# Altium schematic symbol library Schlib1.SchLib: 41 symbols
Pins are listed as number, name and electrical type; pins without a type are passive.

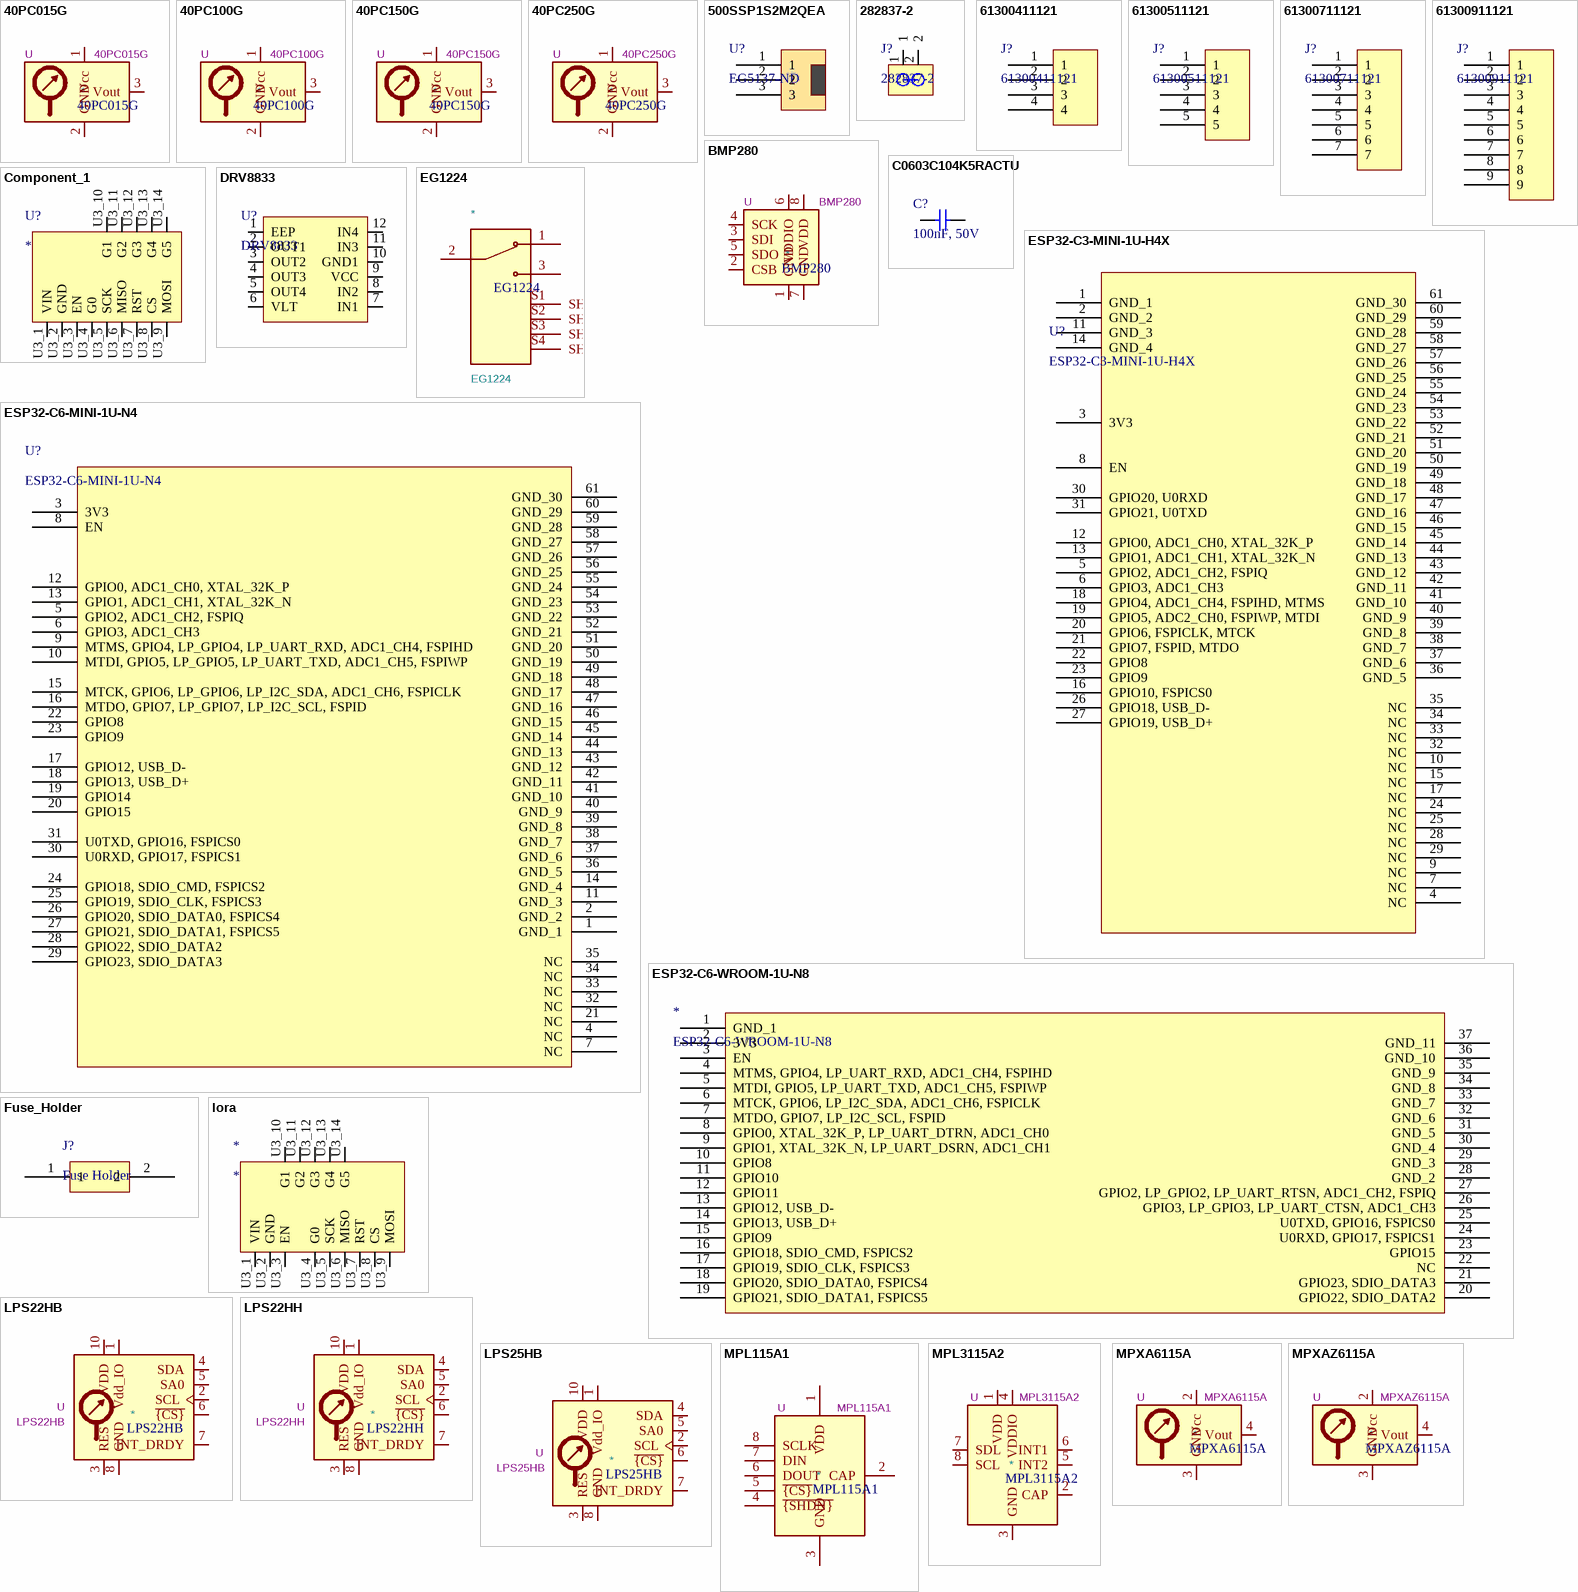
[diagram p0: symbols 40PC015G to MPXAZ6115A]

## 40PC015G
designator *  Reference: U
Gauge pressure sensor, 0 to 15PSI, 5V supply, 0.2% accuracy, integrated signal conditioning, excellent media compatibility; ki_keywords: gage gauge pressure sensor
pins: 1 Vcc, 2 GND, 3 Vout, 4 NC hidden, 5 NC hidden, 6 NC hidden

## 40PC100G
designator *  Reference: U
Gauge pressure sensor, 0 to 100PSI, 5V supply, 0.2% accuracy, integrated signal conditioning, excellent media compatibility; ki_keywords: gage gauge pressure sensor
pins: 1 Vcc, 2 GND, 3 Vout, 4 NC hidden, 5 NC hidden, 6 NC hidden

## 40PC150G
designator *  Reference: U
Gauge pressure sensor, 0 to 150PSI, 5V supply, 0.2% accuracy, integrated signal conditioning, excellent media compatibility; ki_keywords: gage gauge pressure sensor
pins: 1 Vcc, 2 GND, 3 Vout, 4 NC hidden, 5 NC hidden, 6 NC hidden

## 40PC250G
designator *  Reference: U
Gauge pressure sensor, 0 to 250PSI, 5V supply, 0.2% accuracy, integrated signal conditioning, excellent media compatibility; ki_keywords: gage gauge pressure sensor
pins: 1 Vcc, 2 GND, 3 Vout, 4 NC hidden, 5 NC hidden, 6 NC hidden

## 500SSP1S2M2QEA
designator U?, comment EG5137-ND
Switch Slide ON None ON SPDT Extended Top Slide 5A 250VAC 28VDC PC Pins Thru-Hole; Manufacturer: E-Switch; Manufacturer Part Number: 500SSP1S2M2QEA; Actuator Length: 7.239mm; Actuator Material: Nylon; Contact Current Rating: 2A; Contact Resistance: 10mΩ; Contact Voltage Rating (AC): 250V; Electrical Life: 30kcycles; Insulation Resistance: 1GΩ; Max Voltage Rating (DC): 28V; Number of Positions: 1; Sealable: EPOXY; Switch Function: On-On; Switch Travel: 2.16mm; Voltage Rating (AC): 120V
pins: 1, 2, 3

## 282837-2
designator J?
Connector, Terminal Block; Wire Receptacle; 2 Pos.; 16-30 AWG; 0.2 in. CL; Side;; Manufacturer: TE Connectivity; Manufacturer Lifecycle Status: ACTIVE; Approvals: UL; Connector System: Wire-to-Board; Current: 13.5A; Gender: Female; Max Supply Voltage (AC): 250V; Number of Circuits: 2; Number of Levels: 1; Operating Supply Voltage: 300V; Pitch: 5.08mm; Plating: Brass; Tail Length: 3.5mm; Thread Size: M3; Wire/Cable Gauge: 15AWG; Wire Gauge (Max): 28AWG; Wire Gauge (Min): 16AWG
pins: 1, 2

## 61300411121
designator J?
WR-PHD Straight Male, PCB Header, Through Hole, 1 Rows, 4 Contacts, 2.54mm Pitch; Manufacturer: Wurth Elektronik; Manufacturer Part Number: 61300511121; Connector Type: Male Pin; Contact Resistance: 20mΩ; Current Rating: 3A; Insulation Resistance: 1GΩ; Number of Contacts: 5; Operating Supply Voltage: 250V
pins: 1, 2, 3, 4

## 61300511121
designator J?
WR-PHD Straight Male, PCB Header, Through Hole, 1 Rows, 5 Contacts, 2.54mm Pitch; Manufacturer: Wurth Elektronik; Connector Type: Male Pin; Contact Resistance: 20mΩ; Current Rating: 3A; Insulation Resistance: 1GΩ; Number of Contacts: 5; Operating Supply Voltage: 250V
pins: 1, 2, 3, 4, 5

## 61300711121
designator J?
THT Vertical Pin Header WR-PHD, Pitch 2.54 mm, Single Row, 7 pins; Manufacturer: Wurth Elektronik; Connector Type: Male Pin; Contact Resistance: 20mΩ; Current Rating: 3A; Gender: Male; Insulation Resistance: 1GΩ; Number of Contacts: 7; Operating Supply Voltage: 250V; Pitch: 2.54mm
pins: 1, 2, 3, 4, 5, 6, 7

## 61300911121
designator J?
Wr-phd; Series 6130, 2.54MM Pitch 9 Way 1 Row Straight Pin Header, Surface Mount; Manufacturer: Wurth Elektronik; Connector Type: Male Pin; Contact Resistance: 20mΩ; Current Rating: 3A; Gender: Male; Insulation Resistance: 1GΩ; Number of Contacts: 9; Operating Supply Voltage: 250V
pins: 1, 2, 3, 4, 5, 6, 7, 8, 9

## BMP280
designator *  Reference: U
Absolute Barometric Pressure Sensor, LGA-8; ki_keywords: I2C, SPI, pressure, temperature, sensor; ki_fp_filters: Bosch*LGA*2x2.5mm*P0.65mm*
pins: 1 GND, 2 CSB, 3 SDI, 4 SCK, 5 SDO, 6 VDDIO, 7 GND, 8 VDD

## C0603C104K5RACTU
designator C?, comment 100nF, 50V
50V 100nF X7R ±10% 0603 Multilayer Ceramic Capacitors MLCC - SMD/SMT ROHS; Manufacturer: KEMET; Manufacturer Part Number: C0603C104K5RACTU; Dissipation Factor: 2.5%; Temperature Coefficient: 30ppm/°C
pins: 1, 2

## Component_1
designator U?
pins: U3_1 VIN, U3_2 GND "Ground", U3_3 EN "Enable (active high)", U3_4 G0, U3_5 SCK, U3_6 MISO, U3_7 RST, U3_8 CS, U3_9 MOSI, U3_10 G1, U3_11 G2, U3_12 G3, U3_13 G4, U3_14 G5

## DRV8833
designator U?
Motor Driver 6.5V-45VDC In
pins: 1 EEP, 2 OUT1, 3 OUT2, 4 OUT3, 5 OUT4, 6 VLT, 7 IN1 "Chip Select", 8 IN2 "VIN", 9 VCC "VIN", 10 GND1 "Reset", 11 IN3 "Chip Select", 12 IN4 "Chip Select"

## EG1224
designator *
MANUFACTURER: E-Switch
footprint SW_EG1224
pins: 1, 2, 3, S1 SHIELD, S2 SHIELD__1, S3 SHIELD__2, S4 SHIELD__3

## ESP32-C3-MINI-1U-H4X
designator U?
SMD Module, ESP32-C3FH4X, Chip (no antenna); Manufacturer: Espressif Systems; Max Supply Voltage: 3.6V; Min Supply Voltage: 3V; Operating Supply Voltage: 3.3V
footprint ESP32-C3-MINI-1U_EXP
pins: 1 GND_1, 2 GND_2, 3 3V3, 4 NC, 5 GPIO2, ADC1_CH2, FSPIQ, 6 GPIO3, ADC1_CH3, 7 NC, 8 EN, 9 NC, 10 NC, 11 GND_3, 12 GPIO0, ADC1_CH0, XTAL_32K_P, 13 GPIO1, ADC1_CH1, XTAL_32K_N, 14 GND_4, 15 NC, 16 GPIO10, FSPICS0, 17 NC, 18 GPIO4, ADC1_CH4, FSPIHD, MTMS, 19 GPIO5, ADC2_CH0, FSPIWP, MTDI, 20 GPIO6, FSPICLK, MTCK, 21 GPIO7, FSPID, MTDO, 22 GPIO8, 23 GPIO9, 24 NC, 25 NC, 26 GPIO18, USB_D-, 27 GPIO19, USB_D+, 28 NC, 29 NC, 30 GPIO20, U0RXD, 31 GPIO21, U0TXD, 32 NC, 33 NC, 34 NC, 35 NC, 36 GND_5, 37 GND_6, 38 GND_7, 39 GND_8, 40 GND_9, 41 GND_10, 42 GND_11, 43 GND_12, 44 GND_13, 45 GND_14, 46 GND_15, 47 GND_16, 48 GND_17, 49 GND_18, 50 GND_19, 51 GND_20, 52 GND_21, 53 GND_22, 54 GND_23, 55 GND_24, 56 GND_25, 57 GND_26, 58 GND_27, 59 GND_28, 60 GND_29, 61 GND_30

## ESP32-C6-MINI-1U-N4
designator U?
WiFi-Module 802.11 2, 4GHz 150Mb/s; Manufacturer: Espressif Systems; Max Supply Voltage: 3.6V; Min Supply Voltage: 3V; Operating Supply Voltage: 3.3V
pins: 1 GND_1, 2 GND_2, 3 3V3, 4 NC, 5 GPIO2, ADC1_CH2, FSPIQ, 6 GPIO3, ADC1_CH3, 7 NC, 8 EN, 9 MTMS, GPIO4, LP_GPIO4, LP_UART_RXD, ADC1_CH4, FSPIHD, 10 MTDI, GPIO5, LP_GPIO5, LP_UART_TXD, ADC1_CH5, FSPIWP, 11 GND_3, 12 GPIO0, ADC1_CH0, XTAL_32K_P, 13 GPIO1, ADC1_CH1, XTAL_32K_N, 14 GND_4, 15 MTCK, GPIO6, LP_GPIO6, LP_I2C_SDA, ADC1_CH6, FSPICLK, 16 MTDO, GPIO7, LP_GPIO7, LP_I2C_SCL, FSPID, 17 GPIO12, USB_D-, 18 GPIO13, USB_D+, 19 GPIO14, 20 GPIO15, 21 NC, 22 GPIO8, 23 GPIO9, 24 GPIO18, SDIO_CMD, FSPICS2, 25 GPIO19, SDIO_CLK, FSPICS3, 26 GPIO20, SDIO_DATA0, FSPICS4, 27 GPIO21, SDIO_DATA1, FSPICS5, 28 GPIO22, SDIO_DATA2, 29 GPIO23, SDIO_DATA3, 30 U0RXD, GPIO17, FSPICS1, 31 U0TXD, GPIO16, FSPICS0, 32 NC, 33 NC, 34 NC, 35 NC, 36 GND_5, 37 GND_6, 38 GND_7, 39 GND_8, 40 GND_9, 41 GND_10, 42 GND_11, 43 GND_12, 44 GND_13, 45 GND_14, 46 GND_15, 47 GND_16, 48 GND_17, 49 GND_18, 50 GND_19, 51 GND_20, 52 GND_21, 53 GND_22, 54 GND_23, 55 GND_24, 56 GND_25, 57 GND_26, 58 GND_27, 59 GND_28, 60 GND_29, 61 GND_30

## ESP32-C6-WROOM-1U-N8
designator *
ESP32-C6-WROOM-1U Is A ESP32-C6; Manufacturer: Espressif Systems
pins: 1 GND_1, 2 3V3, 3 EN, 4 MTMS, GPIO4, LP_UART_RXD, ADC1_CH4, FSPIHD, 5 MTDI, GPIO5, LP_UART_TXD, ADC1_CH5, FSPIWP, 6 MTCK, GPIO6, LP_I2C_SDA, ADC1_CH6, FSPICLK, 7 MTDO, GPIO7, LP_I2C_SCL, FSPID, 8 GPIO0, XTAL_32K_P, LP_UART_DTRN, ADC1_CH0, 9 GPIO1, XTAL_32K_N, LP_UART_DSRN, ADC1_CH1, 10 GPIO8, 11 GPIO10, 12 GPIO11, 13 GPIO12, USB_D-, 14 GPIO13, USB_D+, 15 GPIO9, 16 GPIO18, SDIO_CMD, FSPICS2, 17 GPIO19, SDIO_CLK, FSPICS3, 18 GPIO20, SDIO_DATA0, FSPICS4, 19 GPIO21, SDIO_DATA1, FSPICS5, 20 GPIO22, SDIO_DATA2, 21 GPIO23, SDIO_DATA3, 22 NC, 23 GPIO15, 24 U0RXD, GPIO17, FSPICS1, 25 U0TXD, GPIO16, FSPICS0, 26 GPIO3, LP_GPIO3, LP_UART_CTSN, ADC1_CH3, 27 GPIO2, LP_GPIO2, LP_UART_RTSN, ADC1_CH2, FSPIQ, 28 GND_2, 29 GND_3, 30 GND_4, 31 GND_5, 32 GND_6, 33 GND_7, 34 GND_8, 35 GND_9, 36 GND_10, 37 GND_11

## Fuse_Holder
designator J?, comment Fuse Holder
pins: 1, 2

## lora
designator *
pins: U3_1 VIN, U3_2 GND "Ground", U3_3 EN "Enable (active high)", U3_4 G0 "VIN", U3_5 SCK "VIN", U3_6 MISO "Reset", U3_7 RST "Chip Select", U3_8 CS "MOSI", U3_9 MOSI "MISO", U3_10 G1, U3_11 G2, U3_12 G3, U3_13 G4, U3_14 G5

## LPS22HB
designator *  Reference: U
MEMS nano pressure sensor, 260-1260 hPa, absolute digital output baromeeter, 24 bit, SPI, I2C, 0.0075 hPa noise rms, ST_HLGA-10L; ki_keywords: mems absolute baromeeter spi i2c pressure; ki_fp_filters: ST?HLGA*2x2mm*P0.5mm*LayoutBorder3x2y*
pins: 1 Vdd_IO, 2 SCL, 3 RES, 4 SDA, 5 SA0, 6 ~{{CS}}, 7 INT_DRDY, 8 GND, 9 GND hidden, 10 VDD

## LPS22HH
designator *  Reference: U
MEMS nano pressure sensor, 260-1260 hPa, absolute digital output baromeeter, 24 bit, SPI, I2C, I3C, 0.65 Pa noise rms, ST_HLGA-10L; ki_keywords: mems absolute baromeeter spi i2c i3c pressure; ki_fp_filters: ST?HLGA*2x2mm*P0.5mm*LayoutBorder3x2y*
pins: 1 Vdd_IO, 2 SCL, 3 RES, 4 SDA, 5 SA0, 6 ~{{CS}}, 7 INT_DRDY, 8 GND, 9 GND hidden, 10 VDD

## LPS25HB
designator *  Reference: U
MEMS nano pressure sensor, 260-1260 hPa, absolute digital output baromeeter, 24 bit, SPI, I2C, 0.01 hPa noise rms, ST_HLGA-10L; ki_keywords: mems absolute baromeeter spi i2c pressure; ki_fp_filters: ST?HLGA*2.5x2.5mm*P0.6mm*LayoutBorder3x2y*
pins: 1 Vdd_IO, 2 SCL, 3 RES, 4 SDA, 5 SA0, 6 ~{{CS}}, 7 INT_DRDY, 8 GND, 9 GND hidden, 10 VDD

## MPL115A1
designator *  Reference: U
SPI Digital Barometer; ki_keywords: spi barometer thermometer mems; ki_fp_filters: NXP*LGA*3x5mm*P1.25mm*H1.2mm*
pins: 1 VDD, 2 CAP, 3 GND, 4 ~{{SHDN}}, 5 ~{{CS}}, 6 DOUT, 7 DIN, 8 SCLK

## MPL3115A2
designator *  Reference: U
I2C precision pressure sensor with altimetry, LGA-8; ki_keywords: pressure sensor altimetry; ki_fp_filters: NXP*LGA*3x5mm*P1.25mm*H1.1mm*
pins: 1 VDD, 2 CAP, 3 GND, 4 VDDIO, 5 INT2, 6 INT1, 7 SDL, 8 SCL

## MPXA6115A
designator *  Reference: U
Absolute pressure sensor, 15 to 115kPa, analog output, integrated signal conditioning, temperature compensated, SO package
pins: 1 NC hidden, 2 Vcc, 3 GND, 4 Vout, 5 NC hidden, 6 NC hidden, 7 NC hidden, 8 NC hidden

## MPXAZ6115A
designator *  Reference: U
Absolute pressure sensor, 15 to 115kPa, analog output, integrated signal conditioning, temperature compensated, media resistant gel, SO package
pins: 1 NC hidden, 2 Vcc, 3 GND, 4 Vout, 5 NC hidden, 6 NC hidden, 7 NC hidden, 8 NC hidden

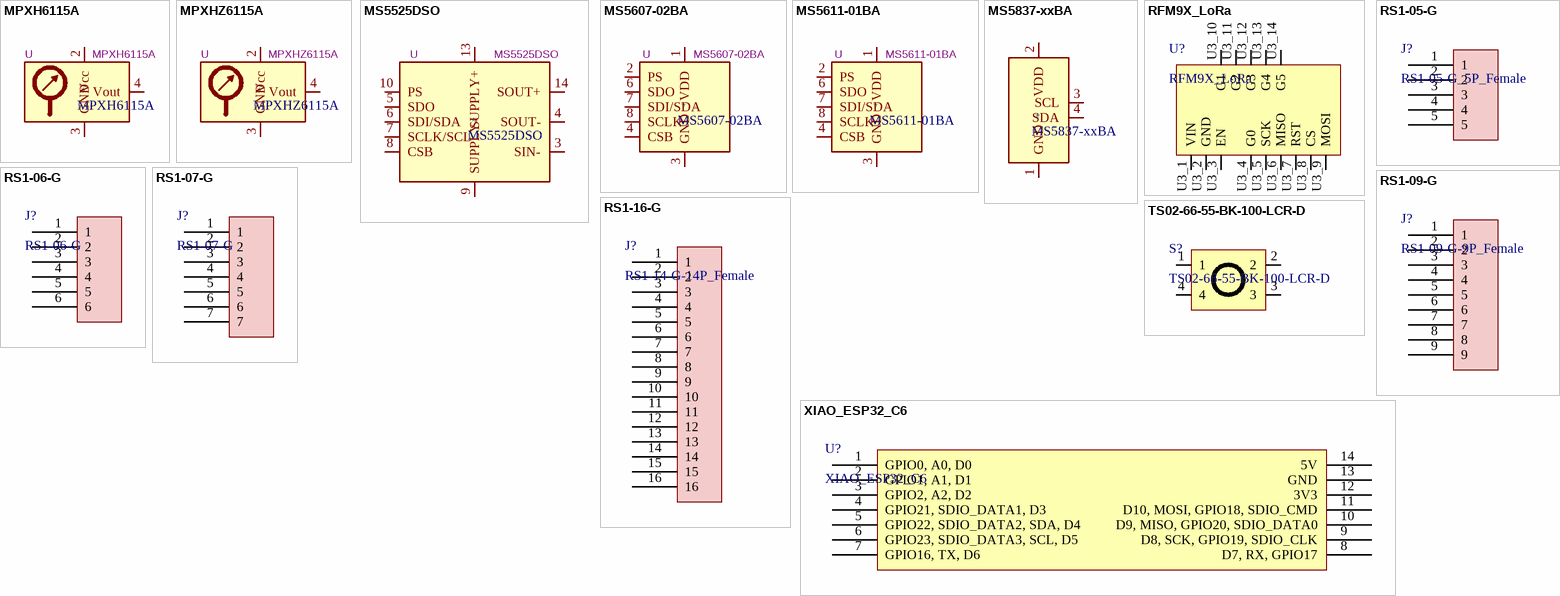
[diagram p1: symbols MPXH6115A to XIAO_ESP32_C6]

## MPXH6115A
designator *  Reference: U
Absolute pressure sensor, 15 to 115kPa, analog output, integrated signal conditioning, temperature compensated, SSO package
pins: 1 NC hidden, 2 Vcc, 3 GND, 4 Vout, 5 NC hidden, 6 NC hidden, 7 NC hidden, 8 NC hidden

## MPXHZ6115A
designator *  Reference: U
Absolute pressure sensor, 15 to 115kPa, analog output, integrated signal conditioning, temperature compensated, media resistant gel, SSO package
pins: 1 NC hidden, 2 Vcc, 3 GND, 4 Vout, 5 NC hidden, 6 NC hidden, 7 NC hidden, 8 NC hidden

## MS5525DSO
designator *  Reference: U
Integrated Digital Pressure Sensor; ki_keywords: 24bit low-power I2C SPI; ki_fp_filters: TE?MS5525DSO*DB* TE?MS5525DSO*SB* TE?MS5525DSO*ST* TE?MS5525DSO*DH* TE?MS5525DSO*FT* TE?MS5525DSO*FB*
pins: 1 SIN- hidden, 2 SOUT- hidden, 3 SIN-, 4 SOUT-, 5 SDO, 6 SDI/SDA, 7 SCLK/SCL, 8 CSB, 9 SUPPLY-, 10 PS, 11 SUPPLY+ hidden, 12 SOUT+ hidden, 13 SUPPLY+, 14 SOUT+

## MS5607-02BA
designator *  Reference: U
Barometric pressure sensor, 20cm resolution, 10 to 1200 mbar, I2C and SPI interface up to 20MHz, LGA-8; ki_keywords: pressure SPI I2C; ki_fp_filters: LGA*3x5mm*P1.25mm*
pins: 1 VDD, 2 PS, 3 GND, 4 CSB, 5 CSB hidden, 6 SDO, 7 SDI/SDA, 8 SCLK

## MS5611-01BA
designator *  Reference: U
Barometric pressure sensor, 10cm resolution, 10 to 1200 mbar, I2C and SPI interface up to 20MHz, LGA-8; ki_keywords: pressure SPI I2C; ki_fp_filters: LGA*3x5mm*P1.25mm*
pins: 1 VDD, 2 PS, 3 GND, 4 CSB, 5 CSB hidden, 6 SDO, 7 SDI/SDA, 8 SCLK

## MS5837-xxBA
designator *
Ultra-small, gel-filled, pressure sensor with stainless steel cap; ki_fp_filters: TE_MS5837*BA*
pins: 1 GND, 2 VDD, 3 SCL, 4 SDA

## RFM9X_LoRa
designator U?
pins: U3_1 VIN, U3_2 GND "Ground", U3_3 EN "Enable (active high)", U3_4 G0 "VIN", U3_5 SCK "VIN", U3_6 MISO "Reset", U3_7 RST "Chip Select", U3_8 CS "MOSI", U3_9 MOSI "MISO", U3_10 G1, U3_11 G2, U3_12 G3, U3_13 G4, U3_14 G5

## RS1-05-G
designator J?, comment RS1-05-G_5P_Female
Connector, Receptacle Strip, 5 Position, 2.54MM Pitch, Single Row; Manufacturer: Adam Tech; Contact Resistance: 20mΩ; Current Rating: 3A; Insulation Resistance: 5GΩ
pins: 1, 2, 3, 4, 5

## RS1-06-G
designator J?
Conn Socket Strip SKT 6 POS 2.54mm Solder ST Top Entry Thru-Hole T/R; Manufacturer: Adam Tech; Contact Resistance: 20mΩ; Current Rating: 3A; Insulation Resistance: 5GΩ; Number of Contacts: 6
pins: 1, 2, 3, 4, 5, 6

## RS1-07-G
designator J?
Connector, Receptacle Strip, 7 Position, 2.54MM Pitch, Single Row; Manufacturer: Adam Tech; Contact Resistance: 20mΩ; Current Rating: 3A; Insulation Resistance: 5GΩ
pins: 1, 2, 3, 4, 5, 6, 7

## RS1-09-G
designator J?, comment RS1-09-G-9P_Female
Connector, Receptacle Strip, 9 Position, 2.54MM Pitch, Single Row; Manufacturer: Adam Tech; Contact Resistance: 20mΩ; Current Rating: 3A; Insulation Resistance: 5GΩ
pins: 1, 2, 3, 4, 5, 6, 7, 8, 9

## RS1-16-G
designator J?, comment RS1-14-G-14P_Female
Connector, Receptacle Strip, 14 Position, 2.54MM Pitch, Single Row; Manufacturer: Adam Tech; Manufacturer Part Number: RS1-09-G; Contact Resistance: 20mΩ; Current Rating: 3A; Insulation Resistance: 5GΩ
pins: 1, 2, 3, 4, 5, 6, 7, 8, 9, 10, 11, 12, 13, 14, 15, 16

## TS02-66-55-BK-100-LCR-D
designator S?
Switch Tactile OFF (ON) SPST Round Button PC Pins 0.05A 12VDC 100000Cycles 1N Thru-Hole Bag; Manufacturer: Same Sky; Contact Resistance: 100mΩ; Electrical Life: 100kcycles; Max Current Rating: 50mA; Max Voltage Rating (DC): 12V; Number of Positions: 1; Operating Force: 980mN
pins: 1, 2 "MOSI2", 3, 4

## XIAO_ESP32_C6
designator U?
seeed studio FCC ID:Z4T-XIAOESP32C6
pins: 1 GPIO0, A0, D0, 2 GPIO1, A1, D1, 3 GPIO2, A2, D2, 4 GPIO21, SDIO_DATA1, D3, 5 GPIO22, SDIO_DATA2, SDA, D4, 6 GPIO23, SDIO_DATA3, SCL, D5, 7 GPIO16, TX, D6, 8 D7, RX, GPIO17, 9 D8, SCK, GPIO19, SDIO_CLK, 10 D9, MISO, GPIO20, SDIO_DATA0, 11 D10, MOSI, GPIO18, SDIO_CMD, 12 3V3, 13 GND, 14 5V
